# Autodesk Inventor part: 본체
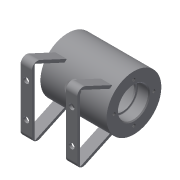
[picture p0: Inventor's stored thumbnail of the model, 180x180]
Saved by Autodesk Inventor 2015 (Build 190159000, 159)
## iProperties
Created: 2021-12
Part Number: 본체
Material: 일반
Document SubType Name: Modeling
Designer: pc-04
Density: 1 g/cm^3
Appearance: 기본값
Mass: 114.708 g
Surface Area: 359.326 cm^2
Volume: 114.708 cm^3
Author: pc-04
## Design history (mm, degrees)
sketch "스케치1"
  geometry: L1 (-35, 55)-(35, 55); L2 (-35, 55)-(-35, 84); L3 (-35, 84)-(35, 84); L4 (35, 84)-(35, 55); 1 further point
  constraints: 8 end point, 2 perpendicular, 1 horizontal, 1 vertical
  dimensions: "d0" = 55 distance from line of point (0, 0) L1; "d1" = 70 distance of L1.start L1.end; "d2" = 35 horizontal distance of point (0, 0) L1.start; "d3" = 58 diameter of L3 L1
revolve "회전1" sketch "스케치1" stored, may be unused: angle "d4" = 90 deg
sketch "스케치2"
  geometry: L1 (-35, 26)-(-35, 84) reference; L2 (-35, 71)-(-23, 71); L3 (-23, 71)-(-23, 69); L4 (-23, 69)-(-21, 69); L5 (-21, 69)-(-21, 76); L6 (-21, 76)-(21, 76); L7 (21, 76)-(21, 69); L8 (21, 69)-(23, 69); L9 (23, 69)-(23, 71); L10 (23, 71)-(35, 71); L11 (-35, 55)-(35, 55); L12 (35, 26)-(35, 84) reference; L13 (-35, 71)-(-35, 55); L14 (35, 71)-(35, 55); 1 further point
  constraints: 24 end point, 6 perpendicular, 5 point on line, 2 midpoint, 1 collinear, 1 horizontal
  dimensions: "d5" = 32 diameter of L2 L11; "d6" = 28 diameter of L4 L11; "d7" = 42 diameter of L6 L11; "d8" = 12 distance of L2.start L2.end; "d9" = 42 distance of L5.end L6.end; "d10" = 2 distance of L3.end L4.end; "d11" = 2 distance of L7.end L8.end; "d12" = 12 distance of L9.end L10.end
revolve "회전2" sketch "스케치2" stored, may be unused: angle "d13" = 90 deg
node "작업 평면1"
sketch "스케치3"
  geometry: L1 (-22.743, -17.993)-(-40, -55); L2 (-40, -55)-(40, -55); L3 (40, -55)-(22.743, -17.993); L4 (20.024, -19.261)-(35.291, -52); L5 (35.291, -52)-(-35.291, -52); L6 (-35.291, -52)-(-20.024, -19.261); A1 r 29 centre (0, 0) between (-22.743, -17.993) and (22.743, -17.993) reference; A2 r 29 centre (0, 0) between (-22.743, -17.993) and (-20.574, -20.438); A3 r 29 centre (0, 0) between (20.574, -20.438) and (22.743, -17.993); 1 further point
  constraints: 12 end point, 6 point on circle, 2 centre point, 2 point on line, 1 coincident, 1 horizontal, 2 other
  dimensions: "d15" = 55 distance from line of L2 A1.centre; "d16" = 65 deg angle of L2 L1; "d17" = 65 deg angle of L2 L3; "d18" = 80 distance of L1.end L2.end; "d19" = 40 horizontal distance of A1.centre L1.end; "d20" = 3 distance between parallel lines of L2 L5
extrude "돌출1" join sketch "스케치3" distance "d21" = 12; taper "d22" = 0 deg
fillet "모깎기1" dims "d23" = 6
sketch "스케치4" dims "d24" = 42
  geometry: C1 r 29 at (0, 0) reference; 3 further points
  constraints: 1 coincident, 1 vertical alignment, 2 other
hole "구멍1" sketch "스케치4" at (0, 21) diameter "d25" = 3.242; stored, may be unused: countersink angle "d29" = 90 deg, drill point angle "d31" = 118 deg; dims "d26" = 8, "d27" = 4, "d28" = 2, "d30" = 10
node "작업 평면2"
sketch "스케치5"
  geometry: L1 (35, 29)-(35, -29) reference; C1 r 5 at (0, 0); 1 further point
  constraints: 1 centre point
  dimensions: "d37" = 10 diameter of C1; "d38" = 35 distance from line of L1 C1.centre
extrude "돌출2" join sketch "스케치5" distance "d39" = 8; taper "d40" = 0 deg
sketch "스케치6"
  geometry: 2 further points
  constraints: 1 coincident
hole "구멍2" sketch "스케치6" at (0, 0) diameter "d41" = 4.917; stored, may be unused: countersink angle "d45" = 90 deg, drill point angle "d47" = 118 deg; dims "d42" = 6, "d43" = 4, "d44" = 2, "d46" = 8
sketch "스케치7"
  geometry: L1 (-30, 30.582)-(-18.974, 30.582); L2 (-30, 30.582)-(-30, 13.051); L3 (0, 0)-(0, 61.164) reference; C1 r 3 at (-6, 13.051); C2 r 3 at (-54, 13.051); C3 r 3 at (-6, 49.051); C4 r 3 at (-54, 49.051)
  constraints: 4 centre point, 4 end point, 1 horizontal, 1 symmetric about line, 1 vertical, 1 other
  dimensions: "d51" = 6 diameter of C1; "d52" = 6 distance from line of L3 C1.centre; "d53" = 6 diameter of C2; "d54" = 48 distance of C1.centre C2.centre; "d55" = 6 diameter of C3; "d56" = 36 distance of C3.centre C1.centre
extrude "돌출3" cut sketch "스케치7" distance "d57" = 8; taper "d58" = 0 deg
fillet "모깎기2" dims "d59" = 0.5
sketch "스케치8"
  geometry: L1 (55, 0)-(13.25, 0); L2 (55, 0)-(23, 11.647); C1 r 16 at (55, 0) reference; 1 further point
  constraints: 4 end point, 1 horizontal
  dimensions: "d60" = 32 horizontal distance of L1.start L2.end; "d61" = 160 deg angle of L1 L2
node "작업 평면3"
sketch "스케치9"
  geometry: C1 r 6 at (0, 0); 1 further point
  constraints: 1 centre point
  dimensions: "d62" = 12 diameter of C1
extrude "돌출4" join sketch "스케치9" distance "d63" = 10; taper "d64" = 0 deg
sketch "스케치10"
  geometry: 2 further points
hole "구멍3" sketch "스케치10" at (0, 0) diameter "d65" = 4.917; stored, may be unused: countersink angle "d69" = 90 deg, drill point angle "d71" = 0 deg; dims "d66" = 15, "d67" = 4, "d68" = 2, "d70" = 15
fillet "모깎기3" dims "d72" = 1
chamfer "모따기1" distance "d73" = 1; stored, may be unused: second distance "d74" = 2, angle "d75" = 45 deg
chamfer "모따기2" distance "d76" = 0.3; stored, may be unused: second distance "d77" = 2, angle "d78" = 45 deg
fillet "모깎기4" dims "d79" = 3
sketch "스케치11"
  geometry: 1 further point
node "작업 평면4"
sketch "스케치12"
  geometry: C1 r 1.5 at (0, 0); 1 further point
  constraints: 1 centre point, 1 coincident
  dimensions: "d81" = 3 diameter of C1
extrude "돌출5" cut sketch "스케치12" distance "d82" = 9; taper "d83" = 0 deg
node "솔리드1"
mirror "대칭1"
pattern_circular "원형 패턴1" dims angle "d33" = 360 deg
mirror "대칭2"
other parameters: "d14" = -5, "d35" = 87
